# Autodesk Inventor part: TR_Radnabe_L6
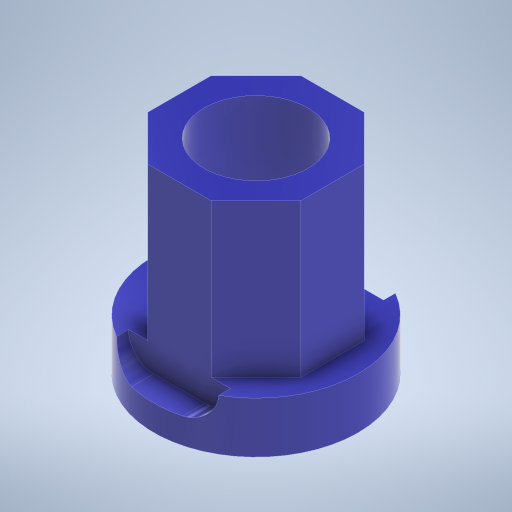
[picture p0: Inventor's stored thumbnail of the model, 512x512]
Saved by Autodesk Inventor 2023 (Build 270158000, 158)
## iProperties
Created: 2023-11
Part Number: TR_Radnabe_L6
Material: PC/ABS-Kunststoff
Document SubType Name: Modeling
Designer: Administrator
Density: 0.357273 g/cm^3
Appearance: Glatt - Marine
Author: Administrator
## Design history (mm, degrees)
sketch "Skizze1"
  geometry: L1 (1.243, -3)-(-1.243, -3); L2 (-1.243, -3)-(-3, -1.243); L3 (-3, -1.243)-(-3, 1.243); L4 (-3, 1.243)-(-1.243, 3); L5 (-1.243, 3)-(1.243, 3); L6 (1.243, 3)-(3, 1.243); L7 (3, 1.243)-(3, -1.243); L8 (3, -1.243)-(1.243, -3); C1 r 2.05 at (0, 0); 2 further points
  constraints: 16 end point, 2 coincident, 1 centre point, 1 horizontal, 17 other
  dimensions: "d0" = 6 distance between parallel lines of L7 L3 (= AchteckUmkreis); "d1" = 4.1 diameter of C1 (= DAchsAufnahme)
extrude "Extrusion1" new body sketch "Skizze1" distance "d2" = 6; taper "d3" = 0 deg
sketch "Skizze2" dims "DAchsAufnahme" = 4.1 [user parameter; used in 1 equation term]
  geometry: C1 r 4 at (0, 0); C2 r 2.05 at (0, 0); 1 further point
  constraints: 2 centre point, 2 coincident
  dimensions: "d4" = 8 diameter of C1
extrude "Extrusion2" join sketch "Skizze2" distance "d5" = 2; taper "d6" = 0 deg
sketch "Skizze3"
  geometry: L1 (-4.243, 6)-(-1.757, 6) reference; L2 (-5, 6)-(-1, 6); L3 (-2, 5)-(-4, 5); L4 (-1.757, 6)-(0, 6) reference; A1 r 1 centre (-4, 6) between (-5, 6) and (-4, 5); A2 r 1 centre (-2, 6) between (-2, 5) and (-1, 6); 11 further points; 1 other entity
  constraints: 4 end point, 4 point on circle, 3 midpoint, 2 centre point, 2 horizontal, 2 tangent, 1 coincident, 1 equal radius, 1 parallel, 1 point on line, 10 other
  dimensions: "d7" = 1 radius of A1 (derived); "d8" = 4 distance of point (-1, 6) point (-5, 6); "d9" = 1 distance between parallel lines of L3 L2
extrude "Extrusion4" cut sketch "Skizze3" distance "d12" = 2; taper "d13" = 0 deg
mirror "Spiegeln2"
node "Volumenkörper1"
other parameters: "Radius" = 2.075 [user parameter], "Fasen" = 0.5 [user parameter], "Dicke" = 0.8 [user parameter], "Breitloch" = 2 [user parameter], "Langloch" = 32 [user parameter], "AchteckUmkreis" = 6 [user parameter; used in 1 equation term], "AchsDurchmesser" = 4 [user parameter], "AchsFase" = 0.5 [user parameter]
